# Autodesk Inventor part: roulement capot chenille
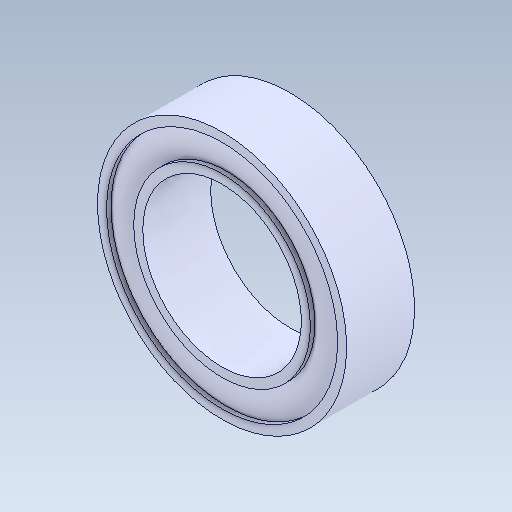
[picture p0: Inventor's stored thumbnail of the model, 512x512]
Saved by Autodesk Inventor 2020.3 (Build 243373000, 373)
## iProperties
Created: 2018-09
Part Number: roulement capot chenille
Material: Générique
Document SubType Name: Modeling
Designer: ficho
Density: 1 g/cm^3
Appearance: Par défaut
Mass: 0.16532 g
Surface Area: 3.10283 cm^2
Volume: 0.16532 cm^3
Sending System: SolidWorks 2015
Last Author: expo-04
Last Saved: 2018-09-21
Author: ficho
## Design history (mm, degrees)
feature "Révolution1"
node "Solide1"
